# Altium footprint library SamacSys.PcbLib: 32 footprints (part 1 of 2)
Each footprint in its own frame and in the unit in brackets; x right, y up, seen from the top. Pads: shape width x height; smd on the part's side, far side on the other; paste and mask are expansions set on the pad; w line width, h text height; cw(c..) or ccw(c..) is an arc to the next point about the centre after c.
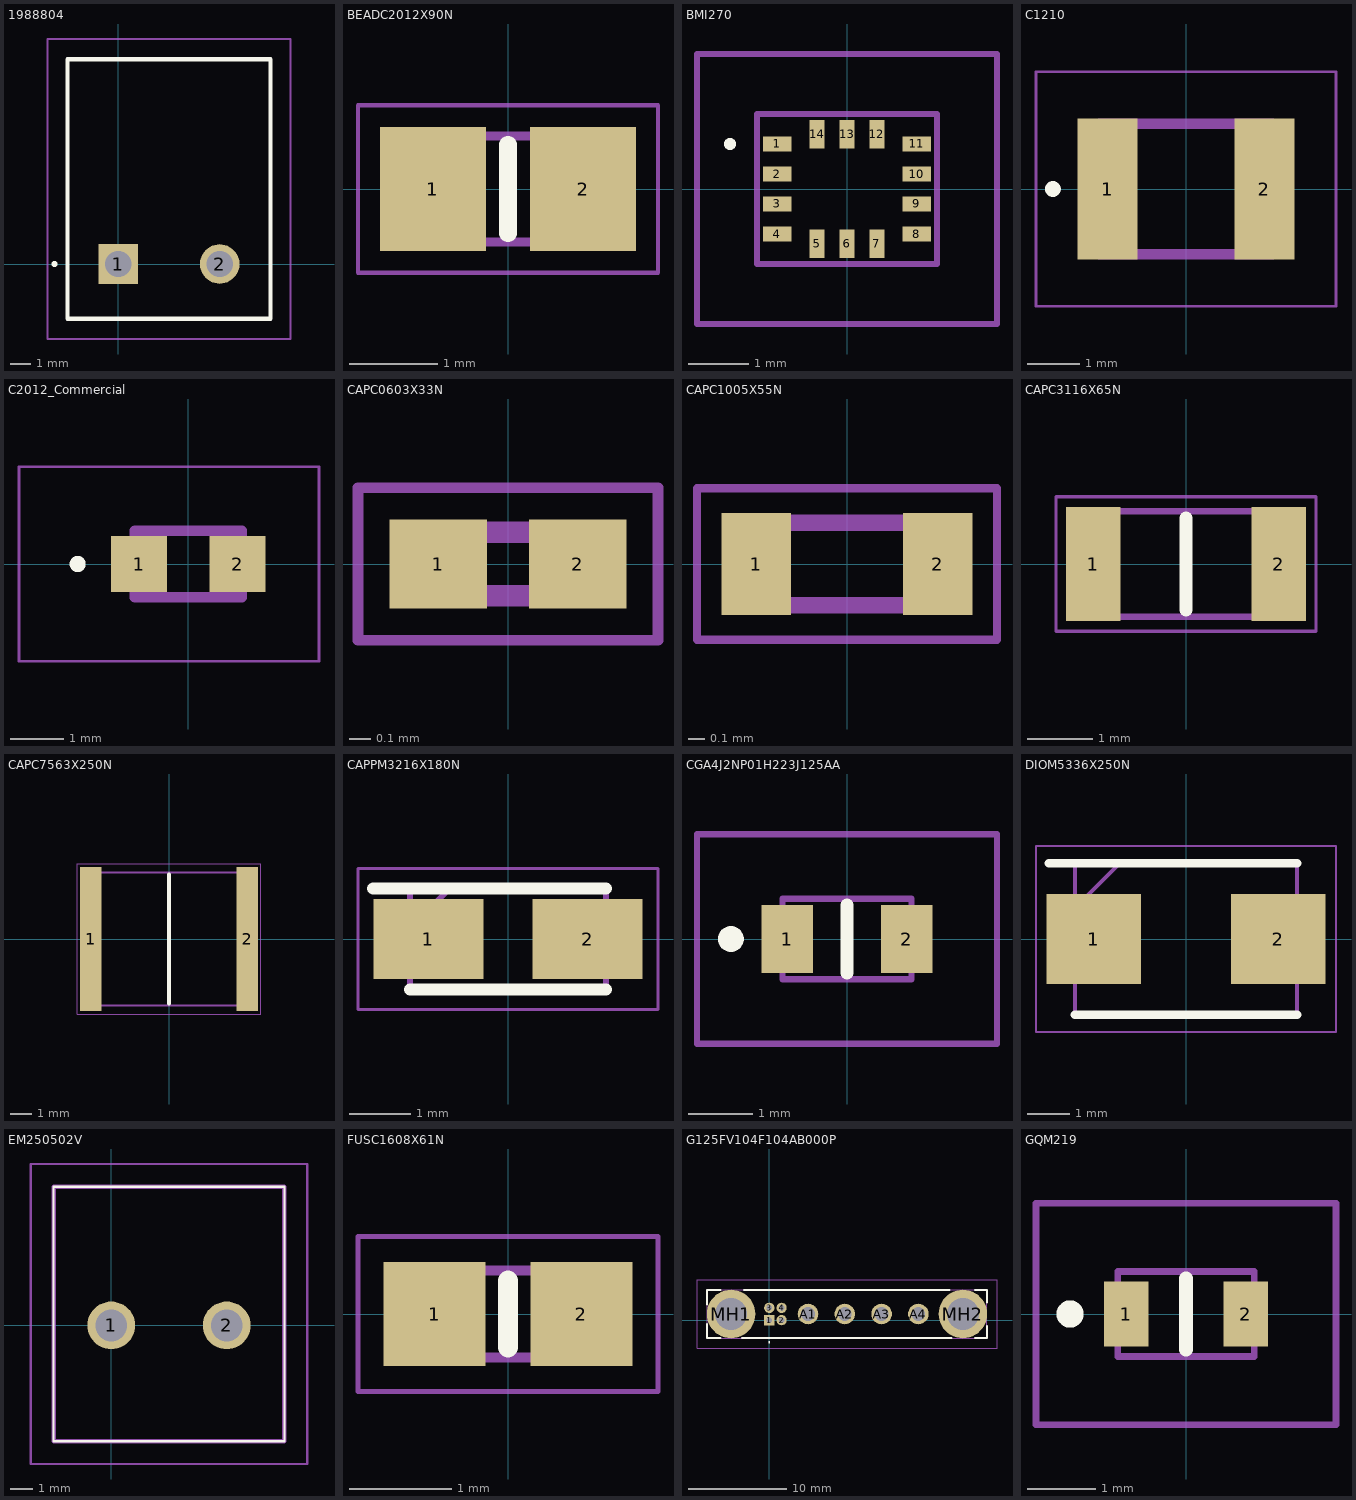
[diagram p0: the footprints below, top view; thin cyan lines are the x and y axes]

## 1988804 [mm]
pads (2):
  rect 1.95x1.95 hole 1.3: 1(0,0)
  round 1.95 hole 1.3: 2(5,0)
Top Overlay:
  lines w0.2: -3.2,0 ccw(c-3.15,0) -3.1,0 ; -3.2,0 cw(c-3.15,0) -3.1,0 ; -3.2,0 ccw(c-3.15,0) -3.1,0 ; -2.5,-2.7 7.5,-2.7 7.5,10.1 -2.5,10.1 -2.5,-2.7
Mechanical 13:
  lines w0.1: -2.5,-2.7 7.5,-2.7 7.5,10.1 -2.5,10.1 -2.5,-2.7
Mechanical 15:
  lines w0.1: -3.5,-3.7 8.5,-3.7 8.5,11.1 -3.5,11.1 -3.5,-3.7
3D body "1988804.stp": height 11.92, standoff -3.5, extent -2.64,-2.71 8.06,10.11

## BEADC2012X90N [mm]
pads (2):
  rect 1.2x1.4 smd: 1(-0.85,0) 2(0.85,0)
Top Overlay:
  lines w0.2: 0,-0.5 0,0.5
Mechanical 13:
  lines w0.1: -1,-0.6 -1,0.6 1,0.6 1,-0.6 -1,-0.6
Mechanical 15:
  lines w0.05: -1.7,-0.95 -1.7,0.95 1.7,0.95 1.7,-0.95 -1.7,-0.95
3D body "742792042.stp": height 0.9, standoff 0, extent -1,-0.6 1,0.6

## BMI270 [mm]
pads (14):
  rect 0.475x0.25 smd mask+0.04: 1(-1.163,0.75) 2(-1.163,0.25) 3(-1.163,-0.25) 4(-1.163,-0.75) 8(1.162,-0.75) 9(1.162,-0.25) 10(1.162,0.25) 11(1.162,0.75)
  rect 0.25x0.475 smd mask+0.04: 5(-0.5,-0.913) 6(0,-0.913) 7(0.5,-0.913) 12(0.5,0.913) 13(0,0.913) 14(-0.5,0.913)
Top Overlay:
  lines w0.1: -2,0.75 ccw(c-1.95,0.75) -1.9,0.75 ccw(c-1.95,0.75) -2,0.75
Mechanical 13:
  lines w0.1: -1.5,-1.25 1.5,-1.25 1.5,1.25 -1.5,1.25 -1.5,-1.25
Mechanical 15:
  lines w0.1: -2.5,-2.25 2.5,-2.25 2.5,2.25 -2.5,2.25 -2.5,-2.25
3D body "BMI270.stp": height 0.83, standoff 0, extent -1.5,-1.25 1.5,1.25

## C1210 [mm]
pads (2):
  rect 1.15x2.7 smd: 1(-1.5,0) 2(1.5,0)
Top Overlay:
  circle w0.2: c-2.55,0 r0.05
Mechanical 13:
  lines w0.2: -1.65,-1.25 -1.65,1.25 1.65,1.25 1.65,-1.25 -1.65,-1.25
Mechanical 15:
  lines w0.05: -2.875,-2.25 -2.875,2.25 2.875,2.25 2.875,-2.25 -2.875,-2.25
3D body "C1210C105K1RACAUTO.stp": height 1.4, standoff 0, extent -1.7,-1.35 1.7,1.35

## C2012_Commercial [mm]
pads (2):
  rect 1.05x1.05 smd: 1(-0.925,0) 2(0.925,0)
Top Overlay:
  circle w0.2: c-2.075,0 r0.05
Mechanical 13:
  lines w0.2: -1,-0.625 -1,0.625 1,0.625 1,-0.625 -1,-0.625
Mechanical 15:
  lines w0.05: -3.175,-1.825 -3.175,1.825 2.45,1.825 2.45,-1.825 -3.175,-1.825
3D body "C2012X7R1V105K085AB.stp": height 1.25, standoff 0, extent -0.96,-0.8 1.04,0.8

## CAPC0603X33N [mm]
pads (2):
  rect 0.46x0.42 smd: 1(-0.33,0) 2(0.33,0)
Mechanical 13:
  lines w0.1: -0.3,-0.15 -0.3,0.15 0.3,0.15 0.3,-0.15 -0.3,-0.15
Mechanical 15:
  lines w0.05: -0.71,-0.36 -0.71,0.36 0.71,0.36 0.71,-0.36 -0.71,-0.36
3D body "CBR02C108B8GAC.stp": height 0.33, standoff 0, extent -0.31,-0.17 0.32,0.16

## CAPC1005X55N [mm]
pads (2):
  rect 0.42x0.62 smd: 1(-0.55,0) 2(0.55,0)
Mechanical 13:
  lines w0.1: -0.5,-0.25 -0.5,0.25 0.5,0.25 0.5,-0.25 -0.5,-0.25
Mechanical 15:
  lines w0.05: -0.91,-0.46 -0.91,0.46 0.91,0.46 0.91,-0.46 -0.91,-0.46
3D body "CGA2B2C0G1H331J050BE.stp": height 0.55, standoff 0, extent -0.5,-0.25 0.5,0.25

## CAPC3116X65N [mm]
pads (2):
  rect 0.83x1.74 smd: 1(-1.41,0) 2(1.41,0)
Top Overlay:
  lines w0.2: 0,-0.7 0,0.7
Mechanical 13:
  lines w0.1: -1.55,-0.8 -1.55,0.8 1.55,0.8 1.55,-0.8 -1.55,-0.8
Mechanical 15:
  lines w0.05: -1.975,-1.02 -1.975,1.02 1.975,1.02 1.975,-1.02 -1.975,-1.02

## CAPC7563X250N [mm]
pads (2):
  rect 1.01x6.81 smd: 1(-3.7,0) 2(3.7,0)
Top Overlay:
  lines w0.2: 0,-3.05 0,3.05
Mechanical 13:
  lines w0.1: -3.75,-3.15 -3.75,3.15 3.75,3.15 3.75,-3.15 -3.75,-3.15
Mechanical 15:
  lines w0.05: -4.355,-3.56 -4.355,3.56 4.355,3.56 4.355,-3.56 -4.355,-3.56
3D body "C7563X7S1H226M230LE.stp": height 2.5, standoff 0, extent -3.75,-3.15 3.75,3.15

## CAPPM3216X180N [mm]
pads (2):
  rect 1.8x1.3 smd: 1(-1.3,0) 2(1.3,0)
Top Overlay:
  lines w0.2: -2.2,0.825 1.6,0.825 ; -1.6,-0.825 1.6,-0.825
Mechanical 13:
  lines w0.1: -1.6,0.175 -0.95,0.825 ; -1.6,-0.825 -1.6,0.825 1.6,0.825 1.6,-0.825 -1.6,-0.825
Mechanical 15:
  lines w0.05: -2.45,-1.15 -2.45,1.15 2.45,1.15 2.45,-1.15 -2.45,-1.15
3D body "TPSA225K035R1500.stp": height 1.8, standoff 0, extent -1.6,-0.825 1.6,0.825

## CGA4J2NP01H223J125AA [mm]
pads (2):
  rect 0.8x1.05 smd: 1(-0.925,0) 2(0.925,0)
Top Overlay:
  lines w0.2: 0,-0.525 0,0.525 ; -1.8,-0.1 ccw(c-1.8,0) -1.8,0.1 ccw(c-1.8,0) -1.8,-0.1
Mechanical 13:
  lines w0.1: -1,-0.625 -1,0.625 1,0.625 1,-0.625 -1,-0.625
Mechanical 15:
  lines w0.1: -2.325,-1.625 -2.325,1.625 2.325,1.625 2.325,-1.625 -2.325,-1.625
3D body "CGA4J1X7R1V475K125AC.stp": height 1.45, standoff 0, extent -1,-0.625 1,0.625

## DIOM5336X250N [mm]
pads (2):
  rect 2.25x2.15 smd: 1(-2.2,0) 2(2.2,0)
Top Overlay:
  lines w0.2: -3.275,1.81 2.648,1.81 ; -2.648,-1.81 2.648,-1.81
Mechanical 13:
  lines w0.1: -2.648,0.735 -1.572,1.81 ; -2.648,-1.81 -2.648,1.81 2.648,1.81 2.648,-1.81 -2.648,-1.81
Mechanical 15:
  lines w0.05: -3.575,-2.22 -3.575,2.22 3.575,2.22 3.575,-2.22 -3.575,-2.22
3D body "B270-13-F.stp": height 2.5, standoff 0, extent -2.648,-1.81 2.648,1.81

## EM250502V [mm]
pads (2):
  round 2.1 hole 1.4: 1(0,0) 2(5.08,0)
Top Overlay:
  lines w0.1: -2.54,-5.1 7.62,-5.1 7.62,6.1 -2.54,6.1 -2.54,-5.1
Mechanical 13:
  lines w0.2: -2.54,-5.1 7.62,-5.1 7.62,6.1 -2.54,6.1 -2.54,-5.1
Mechanical 15:
  lines w0.1: -3.54,-6.1 8.62,-6.1 8.62,7.1 -3.54,7.1 -3.54,-6.1
3D body "EM250502V.stp": height 15.1, standoff -5, extent -2.54,-5.1 7.62,6.1

## FUSC1608X61N [mm]
pads (2):
  rect 1x1.02 smd: 1(-0.72,0) 2(0.72,0)
Top Overlay:
  lines w0.2: 0,-0.325 0,0.325
Mechanical 13:
  lines w0.1: -0.788,-0.425 -0.788,0.425 0.788,0.425 0.788,-0.425 -0.788,-0.425
Mechanical 15:
  lines w0.05: -1.47,-0.76 -1.47,0.76 1.47,0.76 1.47,-0.76 -1.47,-0.76
3D body "0438001.A.stp": height 0.61, standoff 0, extent -0.787,-0.425 0.787,0.425

## G125FV104F104AB000P [mm]
pads (10):
  rect 1.05x1.05 hole 0.55: 1(0,0)
  round 1.05 hole 0.55: 2(1.25,0) 3(0,1.25) 4(1.25,1.25)
  round 2.1 hole 1.4: A1(3.95,0.625) A2(7.7,0.625) A3(11.45,0.625) A4(15.2,0.625)
  round 4.95 hole 3.3: MH1(-3.9,0.625) MH2(19.75,0.625)
Top Overlay:
  lines w0.1: 0,-2.3 cw(c0,-2.25) 0,-2.2 cw(c0,-2.25) 0,-2.3
  lines w0.2: -6.35,-0.4 -6.35,-1.825 -5,-1.825 ; -6.35,1.6 -6.35,3.075 -5,3.075 ; -2.8,-1.8 18.6,-1.825 ; -2.6,3.075 18.4,3.075 ; 21,-1.825 22.2,-1.825 22.2,-0.6 ; 21,3.075 22.2,3.075 22.2,1.8
Mechanical 13:
  lines w0.1: -6.35,-1.825 -6.35,3.075 22.2,3.075 22.2,-1.825 -6.35,-1.825
Mechanical 15:
  lines w0.1: -7.375,-2.85 -7.375,4.1 23.225,4.1 23.225,-2.85 -7.375,-2.85
3D body "G125-FV104F1-04AB000P.stp": height 5.25, standoff -4.9, extent -6.345,-1.83 22.205,3.07

## GQM219 [mm]
pads (2):
  rect 0.65x0.95 smd: 1(-0.875,0) 2(0.875,0)
Top Overlay:
  lines w0.2: 0,-0.525 0,0.525 ; -1.7,-0.1 ccw(c-1.7,0) -1.7,0.1 ccw(c-1.7,0) -1.7,-0.1
Mechanical 13:
  lines w0.1: -1,-0.625 -1,0.625 1,0.625 1,-0.625 -1,-0.625
Mechanical 15:
  lines w0.1: -2.2,-1.625 -2.2,1.625 2.2,1.625 2.2,-1.625 -2.2,-1.625
3D body "GQM2195C2ER20BB12D.stp": height 1, standoff 0, extent -1,-0.625 1,0.625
